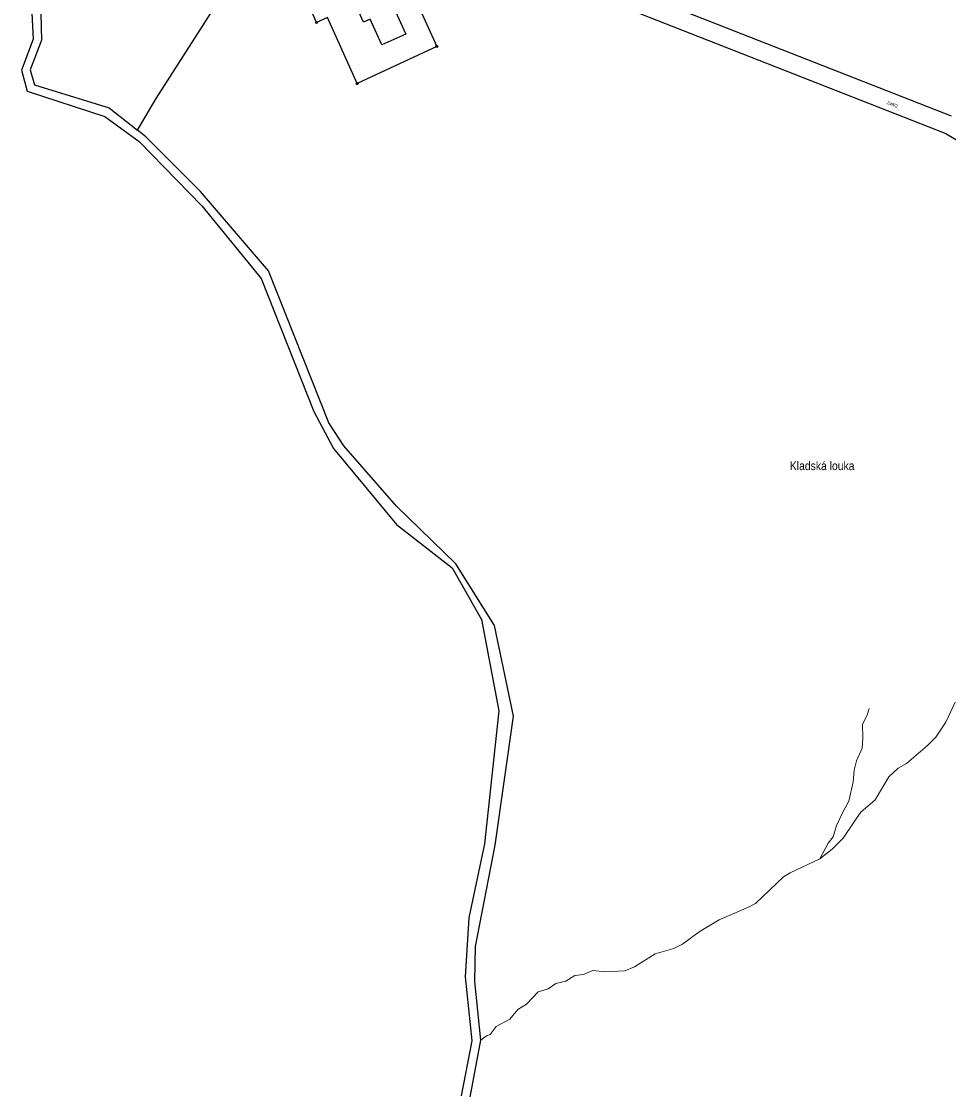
# Model space of a CAD drawing. Extents: x -632162 to -629607, y -1101195 to -1098670.
# Drawn here: x -631734 to -631261, y -1100298 to -1099753 of the extents above; entities that cross this region are included whole.
import ezdxf
from ezdxf.enums import TextEntityAlignment as Align

# ---------------------------------------------------------------- set-up
doc = ezdxf.new("R2010")
doc.units = 0
doc.header["$LTSCALE"] = 0.68
for name, color, linetype, lineweight in [('1', 7, 'Continuous', 25), ('4', 7, 'Continuous', 13), ('7', 7, 'Continuous', 13), ('8', 7, 'Continuous', 25)]:
    doc.layers.add(name, color=color, linetype=linetype, lineweight=lineweight)
doc.layers.add('2', color=7, linetype='Continuous')

msp = doc.modelspace()

# ---------------------------------------------------------------- linework, layer by layer
at = {"layer": '1'}
for points in [[(-631674.85, -1099808.29), (-631665.24, -1099792.15), (-631573.73, -1099649.04)], [(-631573.73, -1099649.04), (-631561.78, -1099657.37), (-631473.19, -1099721.18), (-631427.36, -1099745.46), (-631262.62, -1099810.08), (-631104.85, -1099904.21), (-631080.72, -1099918.6), (-630227.98, -1100408.08)], [(-631259.83, -1099801.22), (-631423.81, -1099736.81), (-631440.94, -1099728.4)], [(-631729.4, -1099735.3), (-631727.98, -1099761.86), (-631734.03, -1099777.73), (-631731.15, -1099788.55), (-631691.5, -1099801.39), (-631674.01, -1099814.07), (-631642.1, -1099846.99), (-631611.74, -1099884.04), (-631584.93, -1099951.83), (-631574.89, -1099970.71), (-631542.75, -1100009.45), (-631514.47, -1100031.61), (-631499.4, -1100058.01), (-631490.61, -1100104.5), (-631497.82, -1100172.32), (-631505.91, -1100210.15), (-631507.73, -1100240.14), (-631504.44, -1100272.86), (-631509.77, -1100300.95)], [(-631724.52, -1099735.45), (-631723.73, -1099762.52), (-631729.47, -1099777.53), (-631727.37, -1099785.28), (-631689.19, -1099797.05), (-631674.85, -1099808.29)], [(-631514.39, -1100469.3), (-631508.99, -1100459.37), (-631486.69, -1100410.32), (-631480.94, -1100391.88), (-631478.56, -1100364.4), (-631484.98, -1100348.32), (-631500.42, -1100327.16), (-631505.24, -1100301.6), (-631499.75, -1100272.48), (-631502.8, -1100242.55), (-631502.56, -1100224.73), (-631492.45, -1100173.01), (-631483.19, -1100107.23), (-631492.79, -1100061), (-631512.51, -1100029.49), (-631542.83, -1100000.08), (-631569.67, -1099969.4), (-631577.25, -1099957.6), (-631608.1, -1099880.09), (-631642.72, -1099839.56), (-631670.52, -1099811.69), (-631674.85, -1099808.29)]]:
    msp.add_lwpolyline(points, dxfattribs=at)
for points in [[(-631531.77, -1099724.17), (-631539.42, -1099727.73), (-631522.28, -1099765.74), (-631562.86, -1099784.63), (-631577.99, -1099750.85), (-631583.61, -1099753.43), (-631596.98, -1099722.7), (-631550.92, -1099702.14), (-631544.63, -1099716.13), (-631537.12, -1099712.75)], [(-631550.19, -1099764.86), (-631556.14, -1099751.74), (-631559.66, -1099753.34), (-631564.42, -1099742.8), (-631560.84, -1099741.19), (-631548.7, -1099735.73), (-631538.06, -1099759.37)]]:
    msp.add_lwpolyline(points, close=True, dxfattribs=at)
at = {"layer": '4'}
for p, q in [((-631302.87, -1100106.78), (-631301.83, -1100103.25)), ((-631262.71, -1100110.22), (-631258, -1100100.11)), ((-631305.15, -1100111.32), (-631302.87, -1100106.78)), ((-631304.95, -1100118.47), (-631305.15, -1100111.32)), ((-631267.81, -1100117.87), (-631262.71, -1100110.22)), ((-631305.35, -1100123.63), (-631304.95, -1100118.47)), ((-631272.05, -1100122.23), (-631267.81, -1100117.87)), ((-631308.22, -1100129.97), (-631305.35, -1100123.63)), ((-631282.8, -1100131.41), (-631272.05, -1100122.23)), ((-631309.46, -1100134.78), (-631308.22, -1100129.97)), ((-631310.01, -1100140.79), (-631309.46, -1100134.78)), ((-631291.71, -1100138.18), (-631286.98, -1100133.73)), ((-631286.98, -1100133.73), (-631282.8, -1100131.41)), ((-631312.19, -1100150.6), (-631310.01, -1100140.79)), ((-631298.8, -1100149.98), (-631291.71, -1100138.18)), ((-631315.12, -1100155.81), (-631312.19, -1100150.6)), ((-631318.5, -1100162.96), (-631315.12, -1100155.81)), ((-631320.14, -1100168.86), (-631318.5, -1100162.96)), ((-631315.1, -1100169.52), (-631308.49, -1100159.66)), ((-631326.95, -1100180.04), (-631322.69, -1100171.95)), ((-631322.69, -1100171.95), (-631320.14, -1100168.86)), ((-631320.62, -1100175.16), (-631315.1, -1100169.52)), ((-631326.95, -1100180.04), (-631320.62, -1100175.16)), ((-631359.8, -1100202.74), (-631345.51, -1100189.2)), ((-631378.25, -1100211.14), (-631363.26, -1100204.63)), ((-631363.26, -1100204.63), (-631359.8, -1100202.74)), ((-631388.4, -1100217.28), (-631378.25, -1100211.14)), ((-631396.87, -1100223.55), (-631388.4, -1100217.28)), ((-631421.48, -1100235.04), (-631410.85, -1100228.48)), ((-631410.85, -1100228.48), (-631401.41, -1100225.82)), ((-631401.41, -1100225.82), (-631396.87, -1100223.55)), ((-631442.67, -1100237.01), (-631436.34, -1100237.65)), ((-631436.34, -1100237.65), (-631426.29, -1100237.19)), ((-631426.29, -1100237.19), (-631421.48, -1100235.04)), ((-631465.41, -1100246.35), (-631461.46, -1100243.56)), ((-631461.46, -1100243.56), (-631456.52, -1100242.45)), ((-631456.52, -1100242.45), (-631451.88, -1100239.55)), ((-631476.56, -1100254.19), (-631470.58, -1100247.92)), ((-631470.58, -1100247.92), (-631465.41, -1100246.35)), ((-631480.92, -1100256.86), (-631476.56, -1100254.19)), ((-631484.92, -1100261.86), (-631480.92, -1100256.86)), ((-631494.97, -1100269.53), (-631491.89, -1100265.46)), ((-631491.89, -1100265.46), (-631484.92, -1100261.86)), ((-631499.75, -1100272.48), (-631496.83, -1100270.28)), ((-631496.83, -1100270.28), (-631494.97, -1100269.53))]:
    msp.add_line(p, q, dxfattribs=at)
for points in [[(-631308.49, -1100159.66), (-631306.05, -1100156.24), (-631298.8, -1100149.98)], [(-631345.51, -1100189.2), (-631342.05, -1100187.07), (-631326.95, -1100180.04)], [(-631451.88, -1100239.55), (-631447.43, -1100238.99), (-631442.67, -1100237.01)]]:
    msp.add_lwpolyline(points, dxfattribs=at)
at = {"layer": '8'}
for centre, radius in [((-631583.61, -1099753.4299), 0.5), ((-631583.61, -1099753.4299), 0.0303), ((-631522.28, -1099765.7399), 0.5), ((-631522.28, -1099765.7399), 0.0303), ((-631562.86, -1099784.6299), 0.5), ((-631562.86, -1099784.6299), 0.0303)]:
    msp.add_circle(centre, radius, dxfattribs=at)

# ---------------------------------------------------------------- texts
at = {"layer": '2'}
msp.add_text('248/2', height=1.7, rotation=339, dxfattribs=at).set_placement((-631290.2606, -1099795.9809), align=Align.CENTER)
at = {"layer": '7', "width": 0.9}
msp.add_text('Kladská louka', height=4.4, dxfattribs=at).set_placement((-631325.739, -1099981.74), align=Align.CENTER)

doc.saveas('drawing.dxf')
